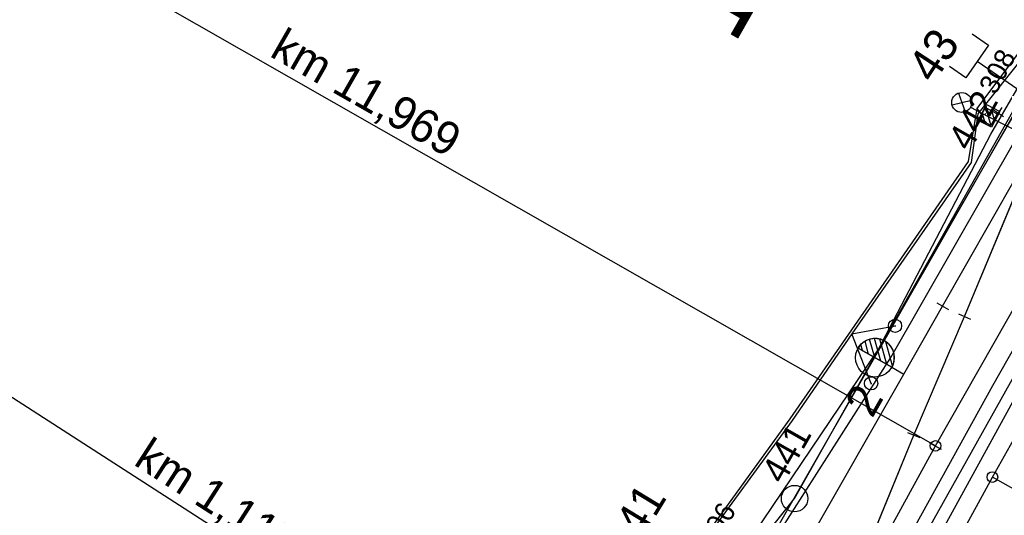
# Model space of a CAD drawing. Extents: x -598638 to -597933, y -1164002 to -1161904.
# Drawn here: x -598254.7 to -598180.3, y -1162925.5 to -1162888 of the extents above; entities that cross this region are included whole.
import ezdxf

# ---------------------------------------------------------------- set-up
doc = ezdxf.new("R2010")
doc.units = 0
for name, color, linetype in [('Vrstva 1', 7, 'Continuous'), ('Vrstva 11', 7, 'Continuous'), ('Vrstva 12', 7, 'Continuous'), ('Vrstva 2', 7, 'Continuous'), ('Vrstva 25', 7, 'Continuous'), ('Vrstva 26', 7, 'Continuous'), ('Vrstva 28', 7, 'Continuous'), ('Vrstva 4', 7, 'Continuous'), ('Vrstva 43', 7, 'Continuous'), ('Vrstva 44', 7, 'Continuous'), ('Vrstva 51', 7, 'Continuous'), ('Vrstva 63', 7, 'Continuous'), ('Vrstva 7', 7, 'Continuous')]:
    doc.layers.add(name, color=color, linetype=linetype)

msp = doc.modelspace()

# ---------------------------------------------------------------- linework, layer by layer
at = {"layer": 'Vrstva 1'}
for p, q in [((-598185.535, -1162920.228), (-598248.646, -1162884.166)), ((-598183.343, -1162910.446), (-598177.649, -1162896.76)), ((-598268.878, -1162907.772), (-598206.72, -1162947.797)), ((-598187.18, -1162919.408), (-598183.343, -1162910.446)), ((-598193.375, -1162934.568), (-598187.18, -1162919.408)), ((-598181.238, -1162922.581), (-598179.637, -1162919.762)), ((-598122.641, -1162956.064), (-598181.238, -1162922.581))]:
    msp.add_line(p, q, dxfattribs=at)
for points in [[(-598185.535, -1162920.228), (-598173.482, -1162899.031), (-598147.832, -1162853.978), (-598130.653, -1162823.786), (-598124.876, -1162813.622), (-598094.683, -1162760.579), (-598072.513, -1162721.65)], [(-598184.995, -1162909.659), (-598177.649, -1162896.76), (-598171.54, -1162886.04)], [(-598187.933, -1162914.793), (-598184.995, -1162909.659)], [(-598202.083, -1162939.655), (-598195.19, -1162927.557), (-598187.933, -1162914.793)], [(-598245.185, -1163146.686), (-598244.89, -1163128.996), (-598244.069, -1163113.383), (-598243.892, -1163111.402), (-598242.508, -1163095.903), (-598240.221, -1163078.173), (-598237.7, -1163063), (-598234.456, -1163047.036), (-598230.819, -1163031.867), (-598224.044, -1163008.196), (-598218.147, -1162990.962), (-598212.612, -1162976.381), (-598210.162, -1162970.38), (-598207.127, -1162963.269), (-598201.66, -1162951.286), (-598200.923, -1162949.67), (-598193.375, -1162934.568), (-598185.535, -1162920.228)], [(-598240.169, -1163146.755), (-598239.921, -1163130.309), (-598239.07, -1163113.566), (-598238.926, -1163111.785), (-598238.259, -1163103.539), (-598237.54, -1163096.536), (-598235.247, -1163078.679), (-598233.075, -1163065.413), (-598229.628, -1163048.216), (-598226.08, -1163033.339), (-598219.335, -1163009.739), (-598213.514, -1162992.625), (-598208.094, -1162978.373), (-598205.572, -1162972.188), (-598202.745, -1162965.549), (-598196.38, -1162951.607), (-598188.854, -1162936.558), (-598181.238, -1162922.581)]]:
    msp.add_lwpolyline(points, dxfattribs=at)
for centre in [(-598185.535, -1162920.228), (-598181.238, -1162922.581)]:
    msp.add_circle(centre, 0.4, dxfattribs=at)
at = {"layer": 'Vrstva 11'}
for p, q in [((-598181.765, -1162894.656), (-598181.351, -1162896.003)), ((-598181.297, -1162894.904), (-598181.103, -1162895.535)), ((-598182.015, -1162895.12), (-598181.818, -1162895.759))]:
    msp.add_line(p, q, dxfattribs=at)
msp.add_lwpolyline([(-598180.884, -1162895.122), (-598181.352, -1162896.006), (-598182.236, -1162895.538), (-598181.768, -1162894.654)], close=True, dxfattribs=at)
for points in [[(-598180.884, -1162895.122), (-598181.352, -1162896.006), (-598182.236, -1162895.538), (-598181.768, -1162894.654), (-598180.884, -1162895.122)], [(-598181.56, -1162895.33), (-598166.09, -1162903.12)]]:
    msp.add_lwpolyline(points, dxfattribs=at)
at = {"layer": 'Vrstva 12'}
for p, q in [((-598182.32, -1162895.64), (-598181.68, -1162894.43)), ((-598181.68, -1162894.43), (-598180.68, -1162894.96)), ((-598180.68, -1162894.96), (-598181.31, -1162896.15)), ((-598181.31, -1162896.15), (-598182.32, -1162895.64))]:
    msp.add_line(p, q, dxfattribs=at)
at = {"layer": 'Vrstva 2'}
for p, q in [((-598185.429, -1162909.412), (-598184.561, -1162909.906)), ((-598183.805, -1162910.254), (-598182.881, -1162910.638)), ((-598189.659, -1162913.815), (-598190.13, -1162912.102)), ((-598189.198, -1162914.077), (-598189.728, -1162912.15)), ((-598188.829, -1162914.287), (-598191.373, -1162912.839)), ((-598191.373, -1162912.839), (-598188.829, -1162914.286)), ((-598191.043, -1162913.027), (-598191.169, -1162912.568)), ((-598190.581, -1162913.29), (-598190.85, -1162912.311)), ((-598190.12, -1162913.552), (-598190.503, -1162912.159)), ((-598188.78, -1162914.185), (-598189.283, -1162912.354)), ((-598188.829, -1162914.286), (-598188.829, -1162914.287)), ((-598188.828, -1162914.288), (-598187.933, -1162914.793)), ((-598187.643, -1162919.219), (-598186.717, -1162919.597)), ((-598185.974, -1162919.988), (-598185.096, -1162920.468))]:
    msp.add_line(p, q, dxfattribs=at)
for points in [[(-598184.995, -1162909.659), (-598177.649, -1162896.76), (-598171.54, -1162886.04)], [(-598183.343, -1162910.446), (-598177.649, -1162896.76)], [(-598202.083, -1162939.655), (-598195.19, -1162927.557), (-598187.933, -1162914.793)], [(-598193.375, -1162934.568), (-598187.18, -1162919.408)], [(-598200.923, -1162949.67), (-598193.375, -1162934.568), (-598185.535, -1162920.228)]]:
    msp.add_lwpolyline(points, dxfattribs=at)
msp.add_circle((-598190.107, -1162913.558), 1.462, dxfattribs=at)
msp.add_arc((-598190.101, -1162913.563), 1.464, 330.39909, 150.35994, dxfattribs=at)
at = {"layer": 'Vrstva 25'}
for p, q in [((-598183.795, -1162893.561), (-598183.294, -1162894.983)), ((-598184.284, -1162894.45), (-598182.82, -1162894.091)), ((-598182.886, -1162894.629), (-598181.56, -1162895.33)), ((-598188.637, -1162911.149), (-598188.537, -1162911.149)), ((-598190.444, -1162915.501), (-598190.344, -1162915.501))]:
    msp.add_line(p, q, dxfattribs=at)
for centre, radius in [((-598183.551, -1162894.274), 0.754), ((-598188.587, -1162911.149), 0.5), ((-598190.394, -1162915.501), 0.5)]:
    msp.add_circle(centre, radius, dxfattribs=at)
at = {"layer": 'Vrstva 26'}
for points in [[(-598177.385, -1162884.508), (-598175.609, -1162885.603), (-598182.404, -1162894.719)], [(-598182.404, -1162894.719), (-598183.077, -1162898.724), (-598191.884, -1162911.461), (-598196.526, -1162918.179)], [(-598182.404, -1162894.719), (-598182.074, -1162895.125), (-598181.791, -1162895.193), (-598181.722, -1162895.085)], [(-598196.526, -1162918.179), (-598204.324, -1162928.997)]]:
    msp.add_lwpolyline(points, dxfattribs=at)
at = {"layer": 'Vrstva 28'}
for points in [[(-598165.351, -1162868.56), (-598166.228, -1162870.696), (-598173.183, -1162882.632), (-598174.441, -1162884.858), (-598175.136, -1162886.062), (-598182.344, -1162895.134), (-598182.836, -1162898.802), (-598191.853, -1162911.765), (-598196.365, -1162918.318), (-598203.621, -1162928.284), (-598209.471, -1162938.339), (-598213.445, -1162942.952), (-598224.077, -1162958.183), (-598230.16, -1162966.29)], [(-598190.394, -1162915.501), (-598191.853, -1162911.765), (-598188.587, -1162911.149)]]:
    msp.add_lwpolyline(points, dxfattribs=at)
at = {"layer": 'Vrstva 4'}
msp.add_lwpolyline([(-598189.853, -1162912.957), (-598181.357, -1162896.669), (-598172.758, -1162881.845), (-598166.709, -1162871.526), (-598158.957, -1162856.49), (-598153.453, -1162843.163), (-598148.638, -1162831.263), (-598144.347, -1162818.421), (-598142.283, -1162807.307), (-598140.136, -1162793.268), (-598139.285, -1162780.248), (-598139.053, -1162767.58), (-598140.211, -1162754.845), (-598141.396, -1162743.83), (-598143.05, -1162731.285)], dxfattribs=at)
at = {"layer": 'Vrstva 43'}
msp.add_lwpolyline([(-598182.756, -1162889.086), (-598181.523, -1162889.94), (-598183.233, -1162892.406), (-598184.465, -1162891.551)], dxfattribs=at)
msp.add_circle((-598196.167, -1162924.209), 1, dxfattribs=at)
at = {"layer": 'Vrstva 44'}
for points in [[(-598295.758, -1163493.483), (-598278.118, -1163452.874), (-598264.209, -1163410.565), (-598254.468, -1163367.19), (-598248.62, -1163321.577), (-598253.497, -1163320.887), (-598249.615, -1163272.581), (-598247.635, -1163222.481), (-598247.486, -1163176.779), (-598247.442, -1163130.148), (-598244.014, -1163084.171), (-598235.33, -1163037.762), (-598224.817, -1163002.559), (-598219.379, -1163002.169), (-598206.652, -1162968.487), (-598191.401, -1162936.053), (-598173.754, -1162904.506), (-598155.689, -1162873.083), (-598136.14, -1162838.446), (-598116.776, -1162804.197)], [(-598217.579, -1162951.29), (-598196.167, -1162924.209), (-598178.917, -1162893.572), (-598182.378, -1162891.173)]]:
    msp.add_lwpolyline(points, dxfattribs=at)
at = {"layer": 'Vrstva 51'}
for points in [[(-598243.76, -1163139.382), (-598243.393, -1163128.836), (-598242.662, -1163113.52), (-598241.121, -1163096.732), (-598238.542, -1163077.297), (-598236.364, -1163063.881), (-598233.006, -1163047.35), (-598229.452, -1163032.186), (-598222.566, -1163008.635), (-598216.788, -1162991.447), (-598211.314, -1162977.141), (-598198.954, -1162949.031), (-598191.954, -1162935.136), (-598181.215, -1162915.654), (-598172.367, -1162900.092), (-598146.639, -1162854.694), (-598125.435, -1162817.431), (-598123.403, -1162813.873), (-598093.874, -1162762.323), (-598071.494, -1162722.83), (-598058.726, -1162701.732), (-598043.403, -1162678.606), (-598026.165, -1162652.845)], [(-598239.095, -1163097.092), (-598236.576, -1163077.501), (-598234.309, -1163064.254), (-598231.064, -1163047.867), (-598227.331, -1163032.522), (-598220.677, -1163009.309), (-598214.847, -1162992.197), (-598209.449, -1162977.846), (-598197.189, -1162949.981), (-598190.09, -1162935.876), (-598179.544, -1162916.618), (-598170.666, -1162900.915), (-598144.793, -1162855.5), (-598123.538, -1162818.503), (-598121.573, -1162814.996), (-598092.208, -1162763.361), (-598069.503, -1162724.253), (-598055.71, -1162703.114), (-598040.468, -1162680.627), (-598023.352, -1162655.056), (-598026.165, -1162652.845)], [(-598247.161, -1162992.683), (-598248.445, -1162991.682), (-598236.167, -1162974.65), (-598221.601, -1162956.026), (-598208.36, -1162939.293), (-598201.425, -1162930.155), (-598189.853, -1162912.957), (-598180.619, -1162896.952), (-598175.616, -1162888.402), (-598174.501, -1162888.256)], [(-598247.161, -1162992.683), (-598234.984, -1162975.74), (-598220.234, -1162956.982), (-598207.085, -1162940.213), (-598200.076, -1162931.081), (-598188.898, -1162913.557), (-598179.448, -1162896.986), (-598174.501, -1162888.256)]]:
    msp.add_lwpolyline(points, dxfattribs=at)
at = {"layer": 'Vrstva 63'}
msp.add_line((-598215.837, -1162958.494), (-598115.28, -1162782.61), dxfattribs=at)
at = {"layer": 'Vrstva 7'}
for p, q in [((-598181.222, -1162894.781), (-598180.39, -1162895.335)), ((-598180.529, -1162894.642), (-598181.083, -1162895.474))]:
    msp.add_line(p, q, dxfattribs=at)

# ---------------------------------------------------------------- texts
at = {"layer": 'Vrstva 1'}
for s, rotation, p in [('km 11,969', 330.25967, (-598235.885, -1162890.735)), ('km 1,117', 327.21761, (-598246.152, -1162921.599))]:
    msp.add_text(s, height=2.5, rotation=rotation, dxfattribs=at).set_placement(p)
at = {"layer": 'Vrstva 11'}
for s, rotation, p in [('43', 56.57203, (-598185.675, -1162892.918)), ('41', 58.65254, (-598207.703, -1162927.304))]:
    msp.add_text(s, height=2.5, rotation=rotation, dxfattribs=at).set_placement(p)
at = {"layer": 'Vrstva 2'}
msp.add_text('2', height=2.5, rotation=60.37942, dxfattribs=at).set_placement((-598190.316, -1162918.199))
at = {"layer": 'Vrstva 25'}
for s, rotation, p in [('308', 62.12448, (-598180.995, -1162893.748)), ('306', 58.54325, (-598202.283, -1162927.981))]:
    msp.add_text(s, height=1.5, rotation=rotation, dxfattribs=at).set_placement(p)
at = {"layer": 'Vrstva 43'}
for s, rotation, p in [('442', 60.32251, (-598182.951, -1162898.04)), ('441', 60.37951, (-598197.031, -1162923.2))]:
    msp.add_text(s, height=2, rotation=rotation, dxfattribs=at).set_placement(p)
at = {"layer": 'Vrstva 7'}
msp.add_text('12,0', height=6, rotation=60.32251, dxfattribs=at).set_placement((-598200.738, -1162889.975))

doc.saveas('drawing.dxf')
